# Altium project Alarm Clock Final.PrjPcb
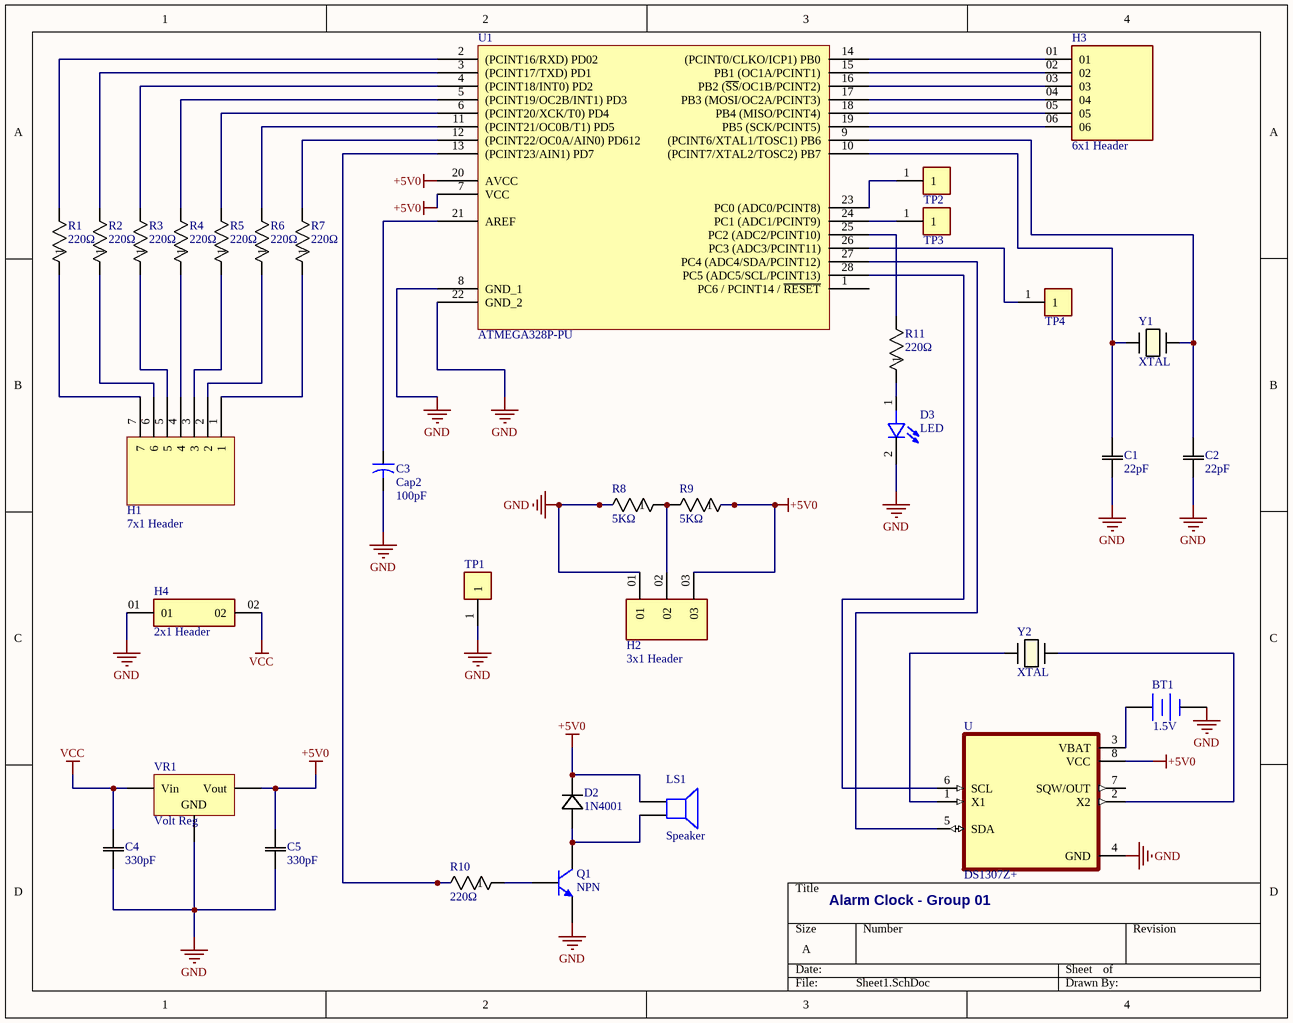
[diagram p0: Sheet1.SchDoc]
1 sheet, 34 parts. Net scope: global (net labels, ports and power ports of the same name join across sheets).
Board file: PCB4.PcbDoc

## Sheet Sheet1.SchDoc: Alarm Clock - Group 01
size A; SheetNumber: 1; SheetTotal: 1

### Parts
BT1  Voltage: 1.5V  [BAT-2]  (hidden comment: Battery)
C1  22pF  [CAP_SK100M050ST_CND]
C2  22pF  [CAP_SK100M050ST_CND]
C3  Cap2  value 100pF  [CAPR5-4X5]
C4  330pF  [CAP_SK100M050ST_CND]
C5  330pF  [CAP_SK100M050ST_CND]
D2  1N4001  [DO-204AL_VIS]
D3  LED  [LED_151054RS03000]
H1  7x1 Header  [TSW-107-XX-XXX-S]
H2  3x1 Header  [SAMTEC_TSW-101-23-S-T]
H3  6x1 Header  [SAMTEC_TSW-106-05-L-S-LL]
H4  2x1 Header  [SAMTEC_MTMM-101-05-T-D-225]
LS1  Speaker  [PIN2]
Q1  NPN  [TO-226-AA]
R1  220Ω  [RES_OD_OHM]
R2  220Ω  [RES_OD_OHM]
R3  220Ω  [RES_OD_OHM]
R4  220Ω  [RES_OD_OHM]
R5  220Ω  [RES_OD_OHM]
R6  220Ω  [RES_OD_OHM]
R7  220Ω  [RES_OD_OHM]
R8  5KΩ  [RES_OD_OHM]
R9  5KΩ  [RES_OD_OHM]
R10  220Ω  [RES_OD_OHM]
R11  220Ω  [RES_OD_OHM]
TP1  Test Point  [KEYSTONE_5000]  (value not drawn)
TP2  Test Point  [KEYSTONE_5000]  (value not drawn)
TP3  Test Point  [KEYSTONE_5000]  (value not drawn)
TP4  Test Point  [KEYSTONE_5000]  (value not drawn)
U  DS1307Z+  [SOIC127P600X175-8N]
U1  ATMEGA328P-PU  [27_DIP_7.62mm]
VR1  Volt Reg  [D2PAK_N]
Y1  XTAL  [XTAL_ABL_ABR]
Y2  XTAL  [XTAL_ABL_ABR]

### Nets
+5V0: C5.2 D2.1 H2.03 LS1.1 R9.1 U.8(VCC) U1.7(VCC) U1.20(AVCC) VR1.3(Vout)
GND: BT1.2(-) C1.1 C2.1 C3.2 C4.1 C5.1 D3.2 H2.01 H4.01 Q1.3(E) R8.2 TP1.1 U.4(GND) U1.8(GND_1) U1.22(GND_2) VR1.2(GND)
VCC: C4.2 H4.02 VR1.1(Vin)
NetBT1_1: BT1.1(+) U.3(VBAT)
NetC1_2: C1.2 U1.10((PCINT7/XTAL2/TOSC2)_PB7) Y1.1
NetC2_2: C2.2 U1.9((PCINT6/XTAL1/TOSC1)_PB6) Y1.2
NetC3_1: C3.1 U1.21(AREF)
NetD2_2: D2.2 LS1.2 Q1.1(C)
NetD3_1: D3.1 R11.1
NetH1_1: H1.1 R7.1
NetH1_2: H1.2 R6.1
NetH1_3: H1.3 R5.1
NetH1_4: H1.4 R4.1
NetH1_5: H1.5 R3.1
NetH1_6: H1.6 R2.1
NetH1_7: H1.7 R1.1
NetH2_02: H2.02 R8.1 R9.2
NetH3_01: H3.01 U1.14((PCINT0/CLKO/ICP1)_PB0)
NetH3_02: H3.02 U1.15(PB1_(OC1A/PCINT1))
NetH3_03: H3.03 U1.16(PB2_(~{SS}/OC1B/PCINT2))
NetH3_04: H3.04 U1.17(PB3_(MOSI/OC2A/PCINT3))
NetH3_05: H3.05 U1.18(PB4_(MISO/PCINT4))
NetH3_06: H3.06 U1.19(PB5_(SCK/PCINT5))
NetQ1_2: Q1.2(B) R10.1
NetR1_2: R1.2 U1.2((PCINT16/RXD)_PD02)
NetR2_2: R2.2 U1.3((PCINT17/TXD)_PD1)
NetR3_2: R3.2 U1.4((PCINT18/INT0)_PD2)
NetR4_2: R4.2 U1.5((PCINT19/OC2B/INT1)_PD3)
NetR5_2: R5.2 U1.6((PCINT20/XCK/T0)_PD4)
NetR6_2: R6.2 U1.11((PCINT21/OC0B/T1)_PD5)
NetR7_2: R7.2 U1.12((PCINT22/OC0A/AIN0)_PD612)
NetR10_2: R10.2 U1.13((PCINT23/AIN1)_PD7)
NetR11_2: R11.2 U1.25(PC2_(ADC2/PCINT10))
NetTP2_1: TP2.1 U1.23(PC0_(ADC0/PCINT8))
NetTP3_1: TP3.1 U1.24(PC1_(ADC1/PCINT9))
NetTP4_1: TP4.1 U1.26(PC3_(ADC3/PCINT11))
NetU_1: U.1(X1) Y2.1
NetU_2: U.2(X2) Y2.2
NetU_5: U.5(SDA) U1.27(PC4_(ADC4/SDA/PCINT12))
NetU_6: U.6(SCL) U1.28(PC5_(ADC5/SCL/PCINT13))

Not connected (* = marked no-connect by the designer): U 7(SQW/OUT); U1 1(PC6_/_PCINT14_/_~{RESET})

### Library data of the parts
BT1 = Battery: Multicell Battery
C1 C2 C4 C5 = SK100M050ST: No Description Available; Mfr_Name: Cornell Dubilier; Type: DEV
C3 = Cap2: Capacitor
D2 = 1N4001-E3/73: No Description Available; Mfr_Name: Vishay; Type: DEV
D3 = 151054RS03000: Red 623nm LED Indication - Discrete 1.9V Radial; MF: Wurth Electronics
H1 = Component_1
H2 = TSW-101-23-S-T
H3 = TSW-106-05-L-S-LL
H4 = MTMM-101-05-T-D-225: Connector Header Through Hole 2 position; MF: Samtec
LS1 = Speaker: Loudspeaker
Q1 = NPN: NPN Bipolar Transistor
R1-R11 = OD27GJE: No Description Available; Mfr_Name: Ohmite
TP1-TP4 = 5000: High Pin Count, Backplane Connectors, Receptacle, Right Angle, Through Hole, 4 Row, 120 Positions, 0 Guide Pin, 2.54mm (0.100in) Pitch; MF: Keystone
U = DS1307Z+: Real Time Clock _RTC_ IC Clock/Calendar 56B IÂ²C, 2-Wire Serial 8-SOIC _0.154, 3.90mm Width_; MF: Maxim Integrated
U1 = ATMEGA328P-PU: ATMEGA328P-PU; 8 bit Microcontroller AVR 20MHz 1; 32kb Flash; 2kb RAM; I2C SPI 2; Manufacturer: Microchip / Atmel; Number of PWM Channels: 6; Number of Timers/Counters: 3; Min Supply Voltage: 1.8V; Max Supply Voltage: 5.5V; Interface: I2C,SPI,UART,USART,2-Wire; Number of I/Os: 23; Oscillator Type: Internal; Data Bus Width: 8b; Number of SPI Channels: 1; Watchdog Timer: Yes; Peripherals: Brown-out Detect/Reset,POR,PWM,WDT
VR1 = Volt Reg: Voltage Regulator
Y1 Y2 = ABL-20.000MHZ-B2: No Description Available; Mfr_Name: Abracon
